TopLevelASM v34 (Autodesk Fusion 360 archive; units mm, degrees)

design "TopLevelASM" references "TopLevelMasterSketch", "BottleLidHolderASM", "HousingASM", "Rotational Option for Nozzle McM", "CYLHousingASM", "WaterSupplySystemASM", "DrainASM"
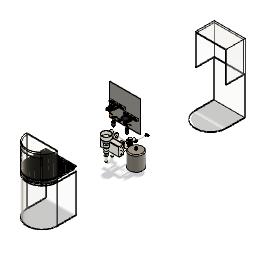
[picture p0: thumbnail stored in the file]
component_insert "Component Insert1"
ground "Ground1"
component_insert "Component Insert3"
ground "Ground2"
ground "Ground3"
ground "Ground6"
position "Position1"
component_insert "Component Insert5"
position "Position2"
component_insert "Component Insert6"
component_insert "Component Insert7"
component_insert "Component Insert8"
joint "Assemble1" alignAngle 0 alignOffsetX 0 alignOffsetY 0 alignOffsetZ 0
component_insert "Component Insert9"
position "Position3"
sketch "Sketch1" plane through (0, 0, -392.3651) normal (0, 0, -1) x axis (-1, 0, 0)
  circle C1 centre (-172.7691, -295.3633) radius 14.2875
  circle C2 centre (-172.7691, -295.3633) radius 15.875
  circle C3 centre (-172.7691, -295.3633) radius 14.2875
  circle C4 centre (-172.7691, -295.3633) radius 15.875
extrude "Extrude1" new body sketch "Sketch1" along normal blind 114.3
joint "Assemble3" alignAngle 180 alignOffsetX 0 alignOffsetY 0 alignOffsetZ 0
position "Position4"
position "Position5"
step "Context"
as_built_joint "As-built5"
position "Position7"
as_built_joint "As-built6"
component_insert "Component Insert12"
ground "Ground12"
as_built_joint "As-built7"

design "FrontPlumbingPanel" references "HousingMasterSketch"
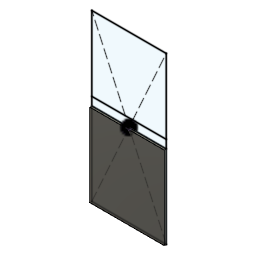
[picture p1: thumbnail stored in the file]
parameter "PlumbingPanelThickness" = 12.7
component_insert "Component Insert"
extrude "Extrude1" new body blind 12.7 (= "PlumbingPanelThickness")

design "LidHolderASM" references "LHGripperShort", "LHRail", "LHRubberMaterial", "LHGripperLong", "LHSlider"
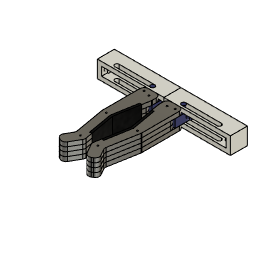
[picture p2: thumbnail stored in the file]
component_insert "Component Insert1"
component_insert "Component Insert2"
component_insert "Component Insert3"
component_insert "Component Insert4"
component_insert "Component Insert5"
component_insert "Component Insert6"
ground "Ground1"
joint "Assemble1" alignAngle 0 alignOffsetX 0 alignOffsetY 0 alignOffsetZ -6.35
joint "Assemble2" alignAngle 0 alignOffsetX 0 alignOffsetY 0 alignOffsetZ 0
joint "Assemble3" alignAngle 0 alignOffsetX 0 alignOffsetY 0 alignOffsetZ 0
joint "Assemble4" alignAngle 0 alignOffsetX 0 alignOffsetY 0 alignOffsetZ 0
joint "Assemble5" alignAngle 0 alignOffsetX 0 alignOffsetY 0 alignOffsetZ 0 SlideMinimum 0 SlideMaximum 53.34
component_insert "Component Insert7"
joint "Assemble8" alignAngle 0 alignOffsetX 0 alignOffsetY 0 alignOffsetZ 0
mirror_component "MirrorComponent1"
derived_instance "DerivedInstance6"
derived_instance "DerivedInstance7"
derived_instance "DerivedInstance1"
derived_instance "DerivedInstance4"
derived_instance "DerivedInstance1"
derived_instance "DerivedInstance4"
derived_instance "DerivedInstance3"
derived_instance "DerivedInstance4"
derived_instance "DerivedInstance5"
derived_instance "DerivedInstance8"
derived_instance "DerivedInstance2"
derived_instance "DerivedInstance10"
derived_instance "DerivedInstance2"
derived_instance "DerivedInstance8"
as_built_joint "As-built1"
ground "Ground2"
joint "Assemble6" alignAngle 0 alignOffsetX 0 alignOffsetY 0 alignOffsetZ 0 SlideMinimum 0 SlideMaximum 53.34
motion_link "MotionLink1" Value1 10.0076 Value2 10.0076
sketch "Sketch1" plane through (0, 0, 0) normal (0, 0, 1) x axis (1, 0, 0)
  circle C1 centre (0, 0) radius 24.13
  circle C2 centre (0, 0) radius 44.45
  point P1 (0, 0)
  point P2 (0, 0)
  coincident P1 P2
  concentric C1 C2
  dimension "d31" diameter C1 = 48.26
  dimension "d32" diameter C2 = 88.9
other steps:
derived_base_feature "Derived Base Feature1"
derived_base_feature "Derived Base Feature1"
derived_base_feature "Derived Base Feature1"
derived_base_feature "Derived Base Feature1"
derived_base_feature "Derived Base Feature1"
derived_base_feature "Derived Base Feature1"
derived_base_feature "Derived Base Feature1"
derived_base_feature "Derived Base Feature1"
derived_base_feature "Derived Base Feature1"
derived_base_feature "Derived Base Feature1"
create_component "CreateComponent1"
create_component "CreateComponent2"
create_component "CreateComponent3"
create_component "CreateComponent5"
create_component "CreateComponent6"
create_component "CreateComponent7"
create_component "CreateComponent8"
create_component "CreateComponent9"
create_component "CreateComponent10"
joint_origin "JointOrigin5"
joint_origin "JointOrigin5"
create_component "CreateComponent12"
create_component "CreateComponent13"
create_component "CreateComponent15"
create_component "CreateComponent16"
create_component "CreateComponent17"

design "BHGripperShort" references "BottleHolderMasterSketch"
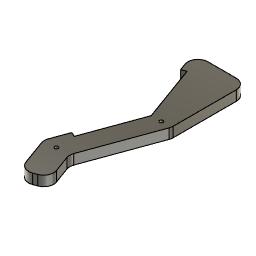
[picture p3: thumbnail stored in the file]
component_insert "Component Insert"
extrude "Extrude1" new body blind 6.35
sketch "Sketch1" plane through (0, 0, 0) normal (0, 0, 1) x axis (1, 0, 0)
  point P2 (32.253, 0)
  point P4 (32.253, 0)
  point P3 (13.189, -47.7364)
  point P5 (13.189, -47.7364)
  coincident P2 P4
  coincident P3 P5
hole "Hole1" HoleDepth 6.35 HoleDiameter 2.2606 TipAngle 118
fillet "Fillet1" radius 6.35
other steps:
create_component "CreateComponent1"

design "TopLevelMasterSketch"
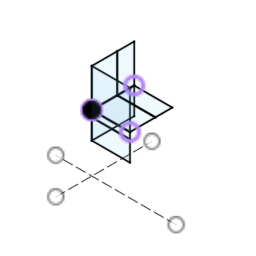
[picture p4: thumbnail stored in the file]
parameter "UIheight" = 457.2 comment "height of the encloser that users will use"
parameter "UIwidth" = 457.2 comment "width of the enclosure that users will interact with"
parameter "UIdepth" = 304.8 comment "depth of the enslosure that users will interract with"
parameter "ElectronicPanelHeight" = 76.2
parameter "ADAHeightOffGround" = 685.8 comment "ADA requirement (usually for the bottom of the water fountain part"
parameter "UnitHeightOffGround" = 368.3
parameter "BackAreaDepth" = 203.2 comment "this is the area behind the UI area where electronics and plumbing can be found"
parameter "Nozheight" = 160.02 comment "height of nozzle including threaded connector"
parameter "Nozdepth" = 38.608 comment "depth of nozzle asm"
parameter "Nozwidth" = 121.92 comment "nozzle width"
sketch "Sketch2" plane through (0, 0, 0) normal (0, 0, 1) x axis (1, 0, 0)
  line L1 (457.2, 0) -> (0, 0)
  line L2 (457.2, 457.2) -> (457.2, 0)
  line L3 (0, 457.2) -> (457.2, 457.2)
  line L4 (0, 0) -> (0, 457.2)
  line L5 (457.2, 0) -> (0, 0)
  line L6 (457.2, -76.2) -> (457.2, 0)
  line L7 (0, -76.2) -> (457.2, -76.2)
  line L8 (0, 0) -> (0, -76.2)
  line L9 (-431.8, -685.8) -> (1010.5119, -685.8)
  line L10 (457.2, -76.2) -> (0, -76.2)
  line L11 (457.2, -317.5) -> (457.2, -76.2)
  line L12 (0, -317.5) -> (457.2, -317.5)
  line L13 (0, -76.2) -> (0, -317.5)
  point P1 (0, 0)
  point P2 (0, 0)
  point P6 (0, 0)
  point P3 (457.2, 0)
  point P5 (0, 457.2)
  point P9 (0, -76.2)
  horizontal L1
  vertical L2
  horizontal L3
  vertical L4
  coincident P1 P2
  horizontal L5
  vertical L6
  horizontal L7
  vertical L8
  coincident P1 P6
  collinear L2 L6
  horizontal L9
  horizontal L10
  vertical L11
  horizontal L12
  vertical L13
  collinear L6 L11
  dimension "d6" distance P2 P3 = 457.2 (= "UIwidth")
  dimension "d7" distance P2 P5 = 457.2 (= "UIheight")
  dimension "d9" distance P6 P9 = 76.2 (= "ElectronicPanelHeight")
  dimension "d12" distance L5 L9 = 685.8 (= "ADAHeightOffGround")
  dimension "d15" distance L9 L12 = 368.3 (= "UnitHeightOffGround")
sketch "Sketch3" plane through (0, 0, 0) normal (1, 0, 0) x axis (0, 0, -1)
  line L1 (304.8, 0) -> (0, 0)
  line L2 (304.8, 457.2) -> (304.8, 0)
  line L3 (0, 457.2) -> (304.8, 457.2)
  line L4 (0, 0) -> (0, 457.2)
  line L5 (508, 0) -> (304.8, 0)
  line L6 (508, 457.2) -> (508, 0)
  line L7 (304.8, 457.2) -> (508, 457.2)
  line L8 (304.8, 0) -> (304.8, 457.2)
  line L9 (720.6658, -685.8) -> (-431.8, -685.8)
  line L10 (508, 0) -> (0, 0)
  line L11 (508, -317.5) -> (508, 0)
  line L12 (0, -317.5) -> (508, -317.5)
  line L13 (0, 0) -> (0, -317.5)
  point P1 (0, 0)
  point P2 (0, 0)
  point P11 (0, 0)
  point P3 (304.8, 0)
  point P6 (508, 0)
  horizontal L1
  vertical L2
  horizontal L3
  vertical L4
  coincident P1 P2
  horizontal L5
  vertical L6
  horizontal L7
  vertical L8
  collinear L3 L7
  horizontal L9
  horizontal L10
  vertical L11
  horizontal L12
  vertical L13
  coincident P1 P11
  collinear L6 L11
  dimension "d16" distance P2 P3 = 304.8 (= "UIdepth")
  dimension "d17" distance L1 L3 = 457.2 (= "UIheight")
  dimension "d19" distance P3 P6 = 203.2 (= "BackAreaDepth")
  dimension "d20" distance L9 L12 = 368.3 (= "UnitHeightOffGround")
  dimension "d21" distance L5 L9 = 685.8 (= "ADAHeightOffGround")
sketch "Sketch4" plane through (0, 0, 0) normal (0, 1, 0) x axis (1, 0, 0)
  line L1 (457.2, 0) -> (0, 0)
  line L2 (457.2, 304.8) -> (457.2, 0)
  line L3 (0, 304.8) -> (457.2, 304.8)
  line L4 (0, 0) -> (0, 304.8)
  line L5 (0, 508) -> (0, 0)
  line L6 (0, 0) -> (457.2, 0)
  line L7 (457.2, 304.8) -> (0, 304.8)
  line L8 (457.2, 508) -> (457.2, 304.8)
  line L9 (0, 508) -> (457.2, 508)
  line L10 (0, 304.8) -> (0, 508)
  point P2 (0, 0)
  point P8 (0, 0)
  point P3 (457.2, 0)
  horizontal L1
  vertical L2
  horizontal L3
  vertical L4
  coincident P2 L5
  coincident P2 P8
  horizontal L7
  vertical L8
  horizontal L9
  vertical L10
  collinear L2 L8
  dimension "d22" distance P2 P3 = 457.2 (= "UIwidth")
  dimension "d23" distance L3 L6 = 304.8 (= "UIdepth")
  dimension "d24" distance L3 L9 = 203.2 (= "BackAreaDepth")

design "HousingASM" references "TopBackHousing", "UIASM", "FrontPlumbingPanel", "BottomHousing", "UIButtonHousing", "HousingMasterSketch"
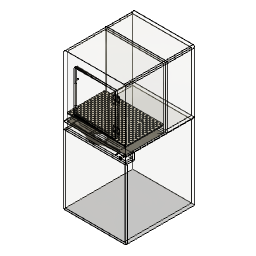
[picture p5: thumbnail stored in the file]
component_insert "Component Insert1"
component_insert "Component Insert2"
component_insert "Component Insert3"
component_insert "Component Insert4"
component_insert "Component Insert5"
ground "Ground1"
ground "Ground2"
position "Position1"
component_insert "Component Insert6"
position "Position2"
position "Position3"
as_built_joint "As-built7"
position "Position4"
as_built_joint "As-built8"
as_built_joint "As-built9"
as_built_joint "As-built10"
position "Position5"
as_built_joint "As-built11"

design "BHRail" references "BottleHolderMasterSketch"
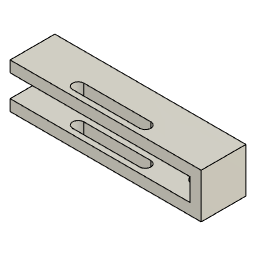
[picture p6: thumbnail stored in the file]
component_insert "Component Insert"
extrude "Extrude1" new body to an object
extrude "Extrude2" to an object
extrude "Extrude3" cut no distance stored
extrude "Extrude4" to an object
sketch "Sketch1" plane through (0, 73.1364, 0) normal (0, -1, 0) x axis (1, 0, 0)
  line L1 (102.1727, 6.35) -> (102.1727, -6.35)
  line L2 (0, 6.35) -> (102.1727, 6.35)
  line L3 (0, -6.35) -> (0, 6.35)
  line L4 (102.1727, -6.35) -> (0, -6.35)
hole "Hole1" HoleDepth 12.7 HoleDiameter 2.2606 TipAngle 118 CBDepth 1.2954 CBDiameter 3.81
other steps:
create_component "CreateComponent1"

design "CYLHousingASM" references "CYLUITopShell", "CYLPlumbingFrontPlate", "CYLPlumbingBackPlate", "CYLButtonPanel", "CYLDoor", "CYLDoorHandle", "CYLGrate", "UIBackPlate", "CYLDrainPlate"
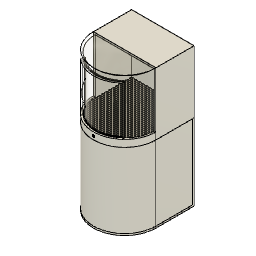
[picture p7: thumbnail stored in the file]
component_insert "Component Insert1"
ground "Ground1"
component_insert "Component Insert2"
as_built_joint "As-built1"
component_insert "Component Insert3"
component_insert "Component Insert4"
as_built_joint "As-built3"
component_insert "Component Insert5"
component_insert "Component Insert6"
position "Position1"
as_built_joint "As-built4"
as_built_joint "As-built6" OffsetX 0 OffsetY 0 OffsetZ 0 AngleZ 0 RotateMinimum 0 RotateMaximum 75
component_insert "Component Insert7"
component_insert "Component Insert8"
component_insert "Component Insert9"
position "Position2"
as_built_joint "As-built7"
as_built_joint "As-built8"
as_built_joint "As-built9"
position "Position3"

design "1/2FIPto3/4FIP"
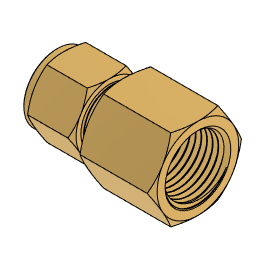
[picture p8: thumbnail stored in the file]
base_feature "Base Feature"
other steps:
create_component "CreateComponent1"

design "PeristalticPump"
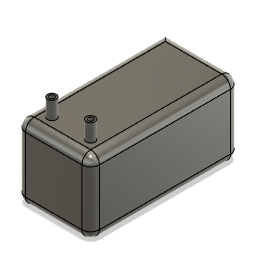
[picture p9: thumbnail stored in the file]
sketch "Sketch1" plane through (0, 0, 0) normal (0, 1, 0) x axis (1, 0, 0)
  line L1 (42, 0) -> (0, 0)
  line L2 (42, -84.4) -> (42, 0)
  line L3 (0, -84.4) -> (42, -84.4)
  line L4 (0, 0) -> (0, -84.4)
  point P1 (0, 0)
  point P2 (0, 0)
  point P3 (42, 0)
  point P5 (0, -84.4)
  horizontal L1
  vertical L2
  horizontal L3
  vertical L4
  coincident P1 P2
  dimension "d1" distance P2 P3 = 42
  dimension "d2" distance P2 P5 = 84.4
extrude "Extrude1" new body sketch "Sketch1" along normal blind 41.9
sketch "Sketch2" plane through (0, 0, 0) normal (0, 1, 0) x axis (1, 0, 0)
  line L1 (0, -84.4) -> (42, -84.4)
  line L2 (0, 0) -> (0, -84.4)
  line L3 (42, -84.4) -> (42, 0)
  circle C1 centre (10, -74.4) radius 2.5
  circle C2 centre (32, -74.4) radius 2.5
  circle C3 centre (10, -74.4) radius 1.5
  circle C4 centre (32, -74.4) radius 1.5
  point P2 (10, -74.4)
  point P3 (32, -74.4)
  concentric C1 C3
  concentric C2 C4
  dimension "d5" diameter C1 = 5
  dimension "d6" diameter C2 = 5
  dimension "d7" distance P2 L1 = 10
  dimension "d8" distance P2 L2 = 10
  dimension "d9" distance P3 L3 = 10 (= "d8")
  dimension "d10" distance P3 L1 = 10 (= "d7")
  dimension "d16" diameter C3 = 3
  dimension "d17" diameter C4 = 3
extrude "Extrude2" add sketch "Sketch2" profile of C1 C2 C3 C4 blind 10 from offset 41.9
fillet "Fillet1" radius 5

design "Water Heater body"
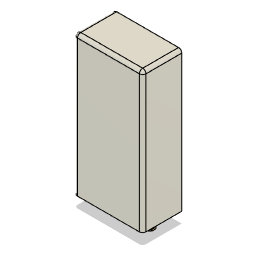
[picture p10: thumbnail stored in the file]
sketch "Sketch1" plane through (0, 0, 0) normal (0, 0, 1) x axis (1, 0, 0)
  line L1 (-66.675, 136.525) -> (66.675, 136.525)
  line L2 (-66.675, -136.525) -> (-66.675, 136.525)
  line L3 (66.675, -136.525) -> (-66.675, -136.525)
  line L4 (66.675, 136.525) -> (66.675, -136.525)
  line L5 (-66.675, -136.525) -> (66.675, 136.525)
  line L6 (66.675, -136.525) -> (-66.675, 136.525)
  point P1 (0, 0)
  point P2 (0, 0)
  point P7 (0, 0)
  point P5 (-66.675, -136.525)
  point P6 (66.675, -136.525)
  point P4 (-66.675, 136.525)
  coincident P1 P2
  horizontal L1
  perpendicular L1 L2
  parallel L1 L3
  parallel L2 L4
  coincident L5 P7
  coincident L6 P7
  coincident P2 P7
  dimension "d1" distance P5 P6 = 133.35
  dimension "d2" distance P4 P5 = 273.05
extrude "Extrude1" new body sketch "Sketch1" profile of L1 L2 L3 L4 along normal blind 76.2 bodies "Heater shell"
sketch "Sketch2" plane through (0, -136.525, 0) normal (0, -1, 0) x axis (1, 0, 0)
  line L1 (66.675, 0) -> (-66.675, 0)
  line L2 (66.675, 76.2) -> (66.675, 0)
  line L3 (-66.675, 76.2) -> (66.675, 76.2)
  line L4 (-66.675, 0) -> (-66.675, 76.2)
  line L5 (66.675, 76.2) -> (-66.675, 76.2)
  line L6 (66.675, 0) -> (66.675, 76.2)
  line L7 (-66.675, 0) -> (66.675, 0)
  line L8 (-66.675, 76.2) -> (-66.675, 0)
  line L9 (-22.225, 38.1) -> (-66.675, 38.1)
  line L10 (22.225, 38.1) -> (-22.225, 38.1)
  line L11 (66.675, 38.1) -> (22.225, 38.1)
  circle C1 centre (-44.45, 38.1) radius 4.7625
  circle C2 centre (0, 38.1) radius 4.7625
  circle C3 centre (44.45, 38.1) radius 4.7625
  point P3 (66.675, 0)
  point P8 (66.675, 0)
  point P5 (-66.675, 76.2)
  point P6 (-66.675, 76.2)
  point P10 (-66.675, 38.1)
  point P13 (-44.45, 38.1)
  point P14 (0, 38.1)
  point P15 (66.675, 38.1)
  point P16 (44.45, 38.1)
  point P11 (-22.225, 38.1)
  point P12 (22.225, 38.1)
  horizontal L5
  vertical L6
  horizontal L7
  vertical L8
  coincident P3 P8
  coincident P5 P6
  midpoint L8 P10
  perpendicular L4 L9
  parallel L9 L10
  midpoint L9 P13
  midpoint L10 P14
  midpoint L6 P15
  midpoint L11 P16
  dimension "d5" distance P10 P11 = 44.45
  dimension "d6" distance P11 P12 = 44.45
  dimension "d7" diameter C1 = 9.525 (= "( 3 / 8 ) * 1 in")
  dimension "d8" diameter C2 = 9.525 (= "( 3 / 8 ) * 1 in")
  dimension "d9" diameter C3 = 9.525 (= "( 3 / 8 ) * 1 in")
sketch "Sketch3" plane through (0, 0, 0) normal (0, 0, -1) x axis (-1, 0, 0)
  line L1 (-66.675, -136.525) -> (-66.675, 136.525)
  line L2 (66.675, -136.525) -> (-66.675, -136.525)
  line L3 (66.675, 136.525) -> (66.675, -136.525)
  line L4 (-66.675, 136.525) -> (66.675, 136.525)
  line L5 (-66.675, -136.525) -> (66.675, -136.525)
  line L6 (-66.675, 136.525) -> (-66.675, -136.525)
  line L7 (66.675, 136.525) -> (-66.675, 136.525)
  line L8 (66.675, -136.525) -> (66.675, 136.525)
  line L9 (-66.675, 136.525) -> (66.675, -136.525)
  line L10 (66.675, 136.525) -> (-66.675, -136.525)
  line L11 (-53.975, 136.525) -> (-66.675, 136.525)
  line L12 (-53.975, 123.825) -> (-53.975, 136.525)
  circle C1 centre (-53.975, 123.825) radius 3.175
  circle C2 centre (53.975, 123.825) radius 3.175
  circle C3 centre (-53.975, -123.825) radius 3.175
  circle C4 centre (53.975, -123.825) radius 3.175
  point P10 (0, 0)
  point P4 (66.675, -136.525)
  point P6 (66.675, -136.525)
  point P1 (0, 0)
  point P12 (-53.975, 123.825)
  point P13 (-53.975, 123.825)
  point P8 (-66.675, 136.525)
  point P11 (-53.975, 136.525)
  horizontal L5
  perpendicular L5 L6
  parallel L5 L7
  parallel L6 L8
  coincident L9 P10
  coincident L10 P10
  coincident P4 P6
  coincident P1 P10
  perpendicular L1 L11
  perpendicular L7 L12
  coincident P12 P13
  dimension "d10" distance P8 P11 = 12.7
  dimension "d11" distance P11 P12 = 12.7
  dimension "d12" diameter C1 = 6.35
  dimension "d15" R-Pattern1-uDistance = 107.95
  dimension "d16" R-Pattern1-vDistance = -247.65
shell "Shell1" innerThickness 3.175
extrude "Extrude2" cut sketch "Sketch3" profile of C1 C2 C3 C4 against normal blind 25.4
extrude "Extrude3" cut sketch "Sketch2" profile of L9 L10 C1 C2 L11 C3 against normal blind 6.35
base_feature "Base Feature1"
base_feature "Base Feature1"
work_plane "WorkPlane1" AlongDistance 0
split "Split1"
remove_body "RemoveBody1"
remove_body "RemoveBody2"
remove_body "RemoveBody3"
copy_paste "CopyPaste1"
fillet "Fillet1" radius 6.35
fillet "Fillet2" radius 6.35
fillet "Fillet3" radius 6.35
joint "Assemble1" alignAngle 0 alignOffsetX 7.62 alignOffsetY 0 alignOffsetZ 0
joint "Assemble2" alignAngle 180 alignOffsetX 2.54 alignOffsetY 5.08 alignOffsetZ 0
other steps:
create_component "CreateComponent1"
create_component "CreateComponent1"
joint_origin "JointOrigin1"
joint_origin "JointOrigin1"
joint_origin "JointOrigin2"
joint_origin "JointOrigin2"
named bodies: "Heater shell"

design "LHRail" references "LidHolderMasterSketch"
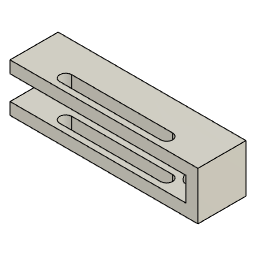
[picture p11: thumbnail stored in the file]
component_insert "Component Insert"
extrude "Extrude1" new body to an object
extrude "Extrude2" to an object
extrude "Extrude3" cut no distance stored
extrude "Extrude4" to an object
sketch "Sketch1" plane through (0, 75.438, 0) normal (0, -1, 0) x axis (1, 0, 0)
  line L1 (92.8878, 6.35) -> (92.8878, -6.35)
  line L2 (0, 6.35) -> (92.8878, 6.35)
  line L3 (0, -6.35) -> (0, 6.35)
  line L4 (92.8878, -6.35) -> (0, -6.35)
hole "Hole1" HoleDepth 12.7 HoleDiameter 2.2606 TipAngle 118 CBDepth 1.2954 CBDiameter 3.81
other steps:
create_component "CreateComponent1"

design "CYLDoorHandle" references "CYLDoor"
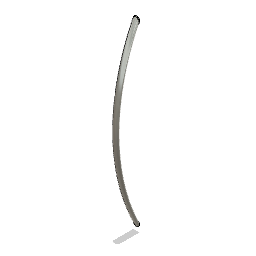
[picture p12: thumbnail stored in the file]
component_insert "Component Insert"
sketch "Sketch3" plane through (0, 0, 0) normal (0, 0, 1) x axis (1, 0, 0)
  circle C1 centre (0, 177.8) radius 3.175
  circle C2 centre (0, 0) radius 3.175
  point P2 (0, 177.8)
  point P3 (0, 0)
  point P1 (0, 0)
  vertical P2 P3
  vertical P1 P3
  equal C1 C2
  coincident P1 P3
  dimension "d8" diameter C1 = 6.35
  dimension "d9" distance P2 P3 = 177.8
sketch "Sketch4" plane through (0, 0, 0) normal (1, 0, 0) x axis (0, 0, -1)
  line L1 (0, 174.625) -> (0, 180.975)
  circle C1 centre (182.7212, 88.9) radius 203.2
  point P4 (0, 177.8)
  point P6 (0, 0)
  coincident P4 C1
  coincident C1 P6
  dimension "d11" diameter C1 = 406.4
sweep "Sweep1" sketch "Sketch3" TwistAngle 0 TaperAngle 0
position "Position1"
sketch "Sketch5" plane through (0, 0, 0) normal (0, 1, 0) x axis (1, 0, 0)
  line L1 (194.359, 157.3581) -> (200.4927, 155.7146)
  line L2 (-56.1526, 7.5404) -> (-54.5091, 13.674)
  arc A1 centre (-1.9171, 209.9502) radius 209.55 clockwise from (200.4927, 155.7146) to (-56.1526, 7.5404)
  arc A2 centre (-1.9171, 209.9502) radius 203.2 clockwise from (194.359, 157.3581) to (-54.5091, 13.674)
extrude "Extrude2" cut sketch "Sketch5" no distance stored
ground "Ground1"
as_built_joint "As-built1"

design "Rotational Option for Nozzle McM" references "One-Way Rotating Flow Joint (3/8)"
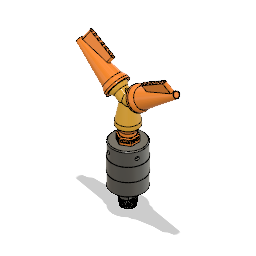
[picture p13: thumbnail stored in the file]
base_feature "Base Feature1" bodies "5307K24"
base_feature "Base Feature1" bodies "10095K36"
position "Position1"
copy_paste "CopyPaste1"
move "Move1"
move "Move2"
move "Move3"
position "Position2"
sketch "Sketch1" plane through (0, -36.992, 0) normal (0, -1, 0) x axis (1, 0, 0)
  circle C1 centre (-43.5581, 0) radius 11.011
  circle C2 centre (-43.5581, 0) radius 10.196
  circle C3 centre (-43.5581, 0) radius 2.54
  concentric C1 C3
  dimension "d1" diameter C3 = 5.08
extrude "Extrude1" cut sketch "Sketch1" profile of C3 against normal blind 127
sketch "Sketch2" plane through (0, -36.992, 0) normal (0, -1, 0) x axis (1, 0, 0)
  circle C1 centre (-43.5581, 0) radius 11.011
  circle C2 centre (-43.5581, 0) radius 10.196
  circle C3 centre (-43.5581, 0) radius 10.196
  circle C4 centre (-43.5581, 0) radius 11.196
  dimension "d4" = 1
base_feature "Base Feature1" bodies "10095K32"
move "Move4"
component_insert "Component Insert"
joint "Assemble2" alignAngle 0 alignOffsetX 0 alignOffsetY 0 alignOffsetZ 0
joint "Assemble3" alignAngle 90 alignOffsetX 0 alignOffsetY 0 alignOffsetZ 0 RotateMinimum 0 RotateMaximum 0
joint "Assemble4" alignAngle 20 alignOffsetX 0 alignOffsetY 0 alignOffsetZ 0
joint "Assemble5" alignAngle 20 alignOffsetX 0 alignOffsetY 0 alignOffsetZ 0
joint "Assemble1" alignAngle 0 alignOffsetX 0 alignOffsetY 0 alignOffsetZ 0 SlideMinimum 0 SlideMaximum 25.4
extrude "Extrude2" add sketch "Sketch2" profile of C1 C2 C3 along normal blind 12.7
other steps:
create_component "CreateComponent1"
create_component "CreateComponent2"
create_component "CreateComponent3"
joint_origin "JointOrigin1"
joint_origin "JointOrigin2"
joint_origin "JointOrigin1"
joint_origin "JointOrigin3"
joint_origin "JointOrigin2"
joint_origin "JointOrigin3"
joint_origin "JointOrigin3"
joint_origin "JointOrigin4"
named bodies: "5307K24", "10095K36", "10095K32"

design "PeristalticPumpASM" references "T-Fitting-3/8-3/8", "PeristalticPump", "DetergentTank"
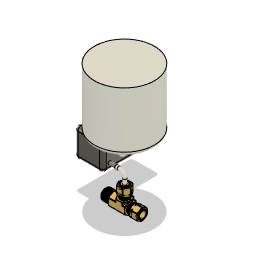
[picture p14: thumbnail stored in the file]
component_insert "Component Insert1"
ground "Ground1"
component_insert "Component Insert4"
position "Position1"
ground "Ground2"
component_insert "Component Insert5"
ground "Ground3"
ground "Ground4"
sketch "Sketch2" plane through (0, 0, 0) normal (0, 0, 1) x axis (1, 0, 0)
  line L1 (-5.7052, 36.576) -> (7.2624, 36.576)
  line L2 (-2.5, 89.1085) -> (2.5, 89.1085)
  line L3 (0, 76.4085) -> (0, 89.1085)
  line L4 (-84.7565, 80.7261) -> (-52.8565, 80.7261)
  line L5 (-8.0505, 74.237) -> (-8.0505, 52.2406)
  line L6 (-11.8605, 52.2406) -> (-8.0505, 52.2406)
  line L7 (-11.8605, 74.237) -> (-8.0505, 74.237)
  line L8 (0.7786, 43.8805) -> (0.7786, 36.576)
  arc A1 centre (-4.3181, 76.4085) radius 4.3181 clockwise from (0, 76.4085) to (-8.0505, 74.237)
  arc A2 centre (-7.594, 43.8805) radius 8.3726 clockwise from (-8.0505, 52.2406) to (0.7786, 43.8805)
  point P7 (0, 89.1085)
  point P16 (0.7786, 36.576)
  point P8 (0, 76.4085)
  point P9 (-8.0505, 52.2406)
  point P10 (-8.0505, 74.237)
  point P14 (-11.8605, 52.2406)
  point P15 (-11.8605, 74.237)
  midpoint L2 P7
  perpendicular L2 L3
  tangent L3 A1
  perpendicular L4 L5
  perpendicular L5 L6
  perpendicular L5 L7
  midpoint L1 P16
  perpendicular L1 L8
  tangent L8 A2
  dimension "d2" distance P7 P8 = 12.7
  dimension "d4" distance P9 P10 = 21.9964
  dimension "d23" distance P9 P14 = 3.81
  dimension "d25" distance P10 P15 = 3.81
sketch "Sketch4" plane through (0.7786, 36.83, 0.2778) normal (0, 1, 0) x axis (0, 0, 1)
  circle C1 centre (0, 0) radius 5.8706
  circle C2 centre (0, 0) radius 4.8514
  circle C3 centre (0, 0) radius 2.5
  circle C4 centre (0, 0) radius 1.5
  concentric C1 C3
  concentric C3 C4
  dimension "d7" diameter C3 = 5
  dimension "d14" diameter C4 = 3
sweep "Sweep1" sketch "Sketch4" TwistAngle 0 TaperAngle 0
sketch "Sketch5" plane through (0, 89.1085, 0) normal (0, -1, 0) x axis (1, 0, 0)
  circle C1 centre (0, 0) radius 5.675
  circle C2 centre (0, 0) radius 2.5
  circle C3 centre (0, 0) radius 0.5
  circle C4 centre (0, 0) radius 2.5
  point P1 (0, 0)
  point P3 (0, 0)
  point P4 (0, 0)
  coincident P1 P3
  coincident P1 P4
  dimension "d15" diameter C3 = 1 (= "mm")
  dimension "d16" diameter C4 = 5
sweep "Sweep2" sketch "Sketch5" TwistAngle 0 TaperAngle 0
ground "Ground5"
joint "Assemble1" alignAngle -90 alignOffsetX 0 alignOffsetY 0 alignOffsetZ 0
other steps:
joint_origin "JointOrigin1"

design "WaterSupplySystemASM" references "3/8compTo3/8MNTP", "PeristalticPumpASM", "T-Fitting-3/8-3/8", "AccumulatorASM", "Water Heater body", "BZW-10-110VAC", "NozzleSetUpASM"
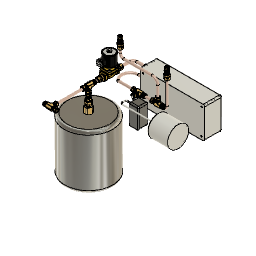
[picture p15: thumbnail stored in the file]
component_insert "Component Insert1"
sketch "Sketch1" plane through (0, 36.83, 0) normal (0, 1, 0) x axis (-1, 0, 0)
  circle C1 centre (-0.7786, 0.2778) radius 5.8706
  circle C2 centre (-0.7786, 0.2778) radius 4.8514
  circle C3 centre (-0.7786, 0.2778) radius 4.8514
  circle C4 centre (-0.7786, 0.2778) radius 3.175
  concentric C3 C4
  dimension "d1" diameter C4 = 6.35
extrude "Extrude1" new body sketch "Sketch1" profile of C2 C3 C4 along normal blind 114.3
component_insert "Component Insert2"
joint "Assemble1" alignAngle 0 alignOffsetX 0 alignOffsetY 0 alignOffsetZ 0
component_insert "Component Insert3"
component_insert "Component Insert4"
component_insert "Component Insert8"
position "Position1"
work_plane "WorkPlane1" AlongDistance 0
position "Position2"
component_insert "Component Insert11"
position "Position5"
sketch "Sketch5" plane through (0, 197.2031, 0) normal (0, 1, 0) x axis (-1, 0, 0)
  circle C1 centre (-0.7786, 0.2778) radius 7.0282
  circle C2 centre (-0.7786, 0.2778) radius 3.9624
  circle C3 centre (-0.7786, 0.2778) radius 3.175
  circle C4 centre (-0.7786, 0.2778) radius 4.7625
  concentric C3 C4
  dimension "d19" diameter C4 = 9.525
extrude "Extrude3" new body sketch "Sketch5" profile of C2 C3 C4 along normal blind 12.7
joint "Assemble3" alignAngle 0 alignOffsetX 0 alignOffsetY 0 alignOffsetZ 10.16
component_insert "Component Insert12"
component_insert "Component Insert13"
joint "Assemble4" alignAngle 180 alignOffsetX -7.62 alignOffsetY 2.54 alignOffsetZ 0
position "Position6"
sketch "Sketch7" plane through (0, 310.8886, 0) normal (0, 1, 0) x axis (-1, 0, 0)
  circle C1 centre (0.43, -0.4775) radius 8
  circle C2 centre (0.43, -0.4775) radius 5.75
  circle C3 centre (0.43, -0.4775) radius 4
  circle C4 centre (0.43, -0.4775) radius 5.5
extrude "Extrude4" new body sketch "Sketch7" profile of C3 C4 along normal blind 12.7 and against normal blind 7.62
sketch "Sketch9" plane through (0, 0, 0) normal (0, 0, 1) x axis (1, 0, 0)
  line L1 (-0.059, 343.4474) -> (-0.059, 323.52)
  line L2 (15.5736, 359.08) -> (35.501, 359.08)
  arc A1 centre (15.5736, 343.4474) radius 15.6326 clockwise from (-0.059, 343.4474) to (15.5736, 359.08)
  point P2 (-0.059, 323.52)
  point P4 (35.501, 359.08)
  point P3 (-0.059, 343.4474)
  point P5 (15.5736, 359.08)
  point P6 (15.5736, 343.4474)
  vertical L1
  horizontal L2
  tangent L2 A1
  dimension "d43" distance P2 L2 = 35.56
  dimension "d44" distance L1 P4 = 35.56
  dimension "d45" angle P3 P5 P6 = 135
sweep "Sweep1" TwistAngle 0 TaperAngle 0
sketch "Sketch10" plane through (35.501, 0, 0) normal (1, 0, 0) x axis (0, 1, 0)
  circle C1 centre (359.451, -0.4775) radius 4
  circle C2 centre (359.451, -0.4775) radius 5.5
  circle C3 centre (359.451, -0.4775) radius 4
  circle C4 centre (359.451, -0.4775) radius 5.5
extrude "Extrude5" add sketch "Sketch10" along normal blind 12.7
joint "Assemble5" alignAngle -90 alignOffsetX 0 alignOffsetY 0 alignOffsetZ 0
position "Position8"
work_plane "WorkPlane2" AlongDistance 299.0342
position "Position9"
work_plane "WorkPlane3" AlongDistance -42.926
sketch "Sketch12" plane through (0, 0, -42.926) normal (0, 0, 1) x axis (1, 0, 0)
  line L1 (23.9471, 352.6133) -> (61.1816, 352.6133)
  line L2 (63.5, 298.4972) -> (6.0432, 298.4972)
  arc A1 centre (23.9471, 322.5936) radius 30.0198 clockwise from (6.0432, 298.4972) to (23.9471, 352.6133)
  horizontal L1
  horizontal L2
  tangent L1 A1
sketch "Sketch13" plane through (60.774, 0, 0) normal (-1, 0, 0) x axis (0, 0, 1)
  circle C1 centre (-43.4161, 358.2258) radius 4.8514
  circle C2 centre (-43.4161, 358.2258) radius 3.9624
  circle C3 centre (-43.4161, 358.2258) radius 3.175
  circle C4 centre (-43.4161, 358.2258) radius 4.7625
  concentric C1 C3
  concentric C3 C4
  dimension "d78" diameter C3 = 6.35
  dimension "d79" diameter C4 = 9.525
component_insert "Component Insert16"
position "Position10"
joint "Assemble10" alignAngle 180 alignOffsetX 0 alignOffsetY 0 alignOffsetZ 0
joint "Assemble11" alignAngle -90 alignOffsetX 0 alignOffsetY 0 alignOffsetZ 0
sketch "Sketch16" plane through (90.9486, 311.8356, -43.6939) normal (0, 0, 1) x axis (-1, 0, 0)
  line L1 (0, 91.44) -> (0, 88.9)
  line L2 (-147.32, 96.52) -> (-4.8749, 96.52)
  line L3 (-251.8787, 109.1301) -> (-251.8787, -7.7623)
  arc A1 centre (-5.0843, 91.44) radius 5.0843 clockwise from (-4.8749, 96.52) to (0, 91.44)
  point P2 (0, 88.9)
  point P5 (-147.32, 96.52)
  vertical L1
  perpendicular L1 L2
  tangent L1 A1
  vertical L3
  dimension "d117" distance P2 L3 = 251.8787
  dimension "d118" distance P2 P5 = 147.32
sweep "Sweep4" TwistAngle 0 TaperAngle 0
joint "Assemble13" alignAngle -90 alignOffsetX 0 alignOffsetY 0 alignOffsetZ 0
sketch "Sketch17" plane through (118.618, 0, 0) normal (1, 0, 0) x axis (0, 1, 0)
  circle C1 centre (292.8847, -43.4161) radius 7.0282
  circle C2 centre (292.8847, -43.4161) radius 3.9624
  circle C3 centre (292.8847, -43.4161) radius 4.7625
  circle C4 centre (292.8847, -43.4161) radius 3.175
  concentric C1 C3
  concentric C3 C4
  dimension "d129" diameter C4 = 6.35
  dimension "d130" diameter C3 = 9.525
extrude "Extrude8" new body sketch "Sketch17" profile of C2 C3 C4 along normal blind 50.8
component_insert "Component Insert17"
joint "Assemble14" alignAngle 90 alignOffsetX 0 alignOffsetY 0 alignOffsetZ 0
sketch "Sketch18" plane through (0, 299.0342, 0) normal (0, 1, 0) x axis (1, 0, 0)
  line L1 (170.7316, -25.6891) -> (170.7316, 18.2038)
  line L2 (26.5745, -48.5385) -> (147.3117, -48.5385)
  line L3 (11.9955, -78.2355) -> (11.9955, -63.4661)
  line L4 (212.3507, -78.0535) -> (212.3507, 31.7721)
  line L5 (341.8304, -88.6121) -> (341.8304, 1.9611)
  line L6 (199.1099, 46.2076) -> (196.0232, 46.2076)
  arc A1 centre (26.9273, -63.4661) radius 14.9318 clockwise from (11.9955, -63.4661) to (26.5745, -48.5385)
  arc A2 centre (147.3117, -25.1114) radius 23.427 clockwise from (170.7316, -25.6891) to (147.3117, -48.5385)
  arc A3 centre (199.1099, 32.9173) radius 13.2903 clockwise from (199.1099, 46.2076) to (212.3507, 31.7721)
  vertical L1
  horizontal L2
  vertical L3
  tangent L3 A1
  tangent L2 A2
  vertical L4
  vertical L5
  perpendicular L3 L6
  tangent L6 A3
  dimension "d168" distance L3 L4 = 200.3552
sketch "Sketch20" plane through (0, 0, -30.4621) normal (0, 0, 1) x axis (-1, 0, 0)
  circle C1 centre (-170.688, -292.8847) radius 4.8514
  circle C2 centre (-170.688, -292.8847) radius 3.9624
  circle C3 centre (-170.688, -292.8847) radius 3.175
  circle C4 centre (-170.688, -292.8847) radius 4.7625
  concentric C1 C3
  concentric C1 C4
  dimension "d137" diameter C3 = 6.35
  dimension "d138" diameter C4 = 9.525
extrude "Extrude9" new body sketch "Sketch20" profile of C2 C3 C4 along normal blind 19.05
sketch "Sketch21" plane through (199.136, 0, 0) normal (1, 0, 0) x axis (0, 1, 0)
  circle C1 centre (292.8847, -43.4161) radius 7.0282
  circle C2 centre (292.8847, -43.4161) radius 3.9624
  circle C3 centre (292.8847, -43.4161) radius 4.7625
  circle C4 centre (292.8847, -43.4161) radius 3.175
  concentric C1 C3
  concentric C1 C4
  dimension "d141" diameter C4 = 6.35
  dimension "d142" diameter C3 = 9.525
extrude "Extrude10" new body sketch "Sketch21" profile of C2 C3 C4 along normal blind 2.54
sweep "Sweep5" TwistAngle 0 TaperAngle 0
sweep "Sweep6" TwistAngle 0 TaperAngle 0
joint "Assemble16" alignAngle 0 alignOffsetX 0 alignOffsetY 0 alignOffsetZ 0
joint "Assemble17" alignAngle -1 alignOffsetX 0 alignOffsetY 0 alignOffsetZ 0
position "Position11"
sketch "Sketch22" plane through (0, 320.2431, -0.8839) normal (0, -1, 0.0028) x axis (1, 0, 0)
  line L1 (68.9973, 23.7715) -> (335.6973, 23.7715)
  line L2 (68.9973, -109.5785) -> (68.9973, 23.7715)
  line L3 (335.6973, -109.5785) -> (68.9973, -109.5785)
  line L4 (342.0473, 17.4215) -> (342.0473, -103.2285)
  line L5 (215.9153, 88.9) -> (203.2, 88.9)
  line L6 (215.9153, 77.9385) -> (215.9153, 88.9)
  line L7 (203.2, 77.9385) -> (215.9153, 77.9385)
  line L8 (203.2, 88.9) -> (203.2, 77.9385)
  arc A1 centre (335.6973, 17.4215) radius 6.35 clockwise from (335.6973, 23.7715) to (342.0473, 17.4215)
  arc A2 centre (335.6973, -103.2285) radius 6.35 clockwise from (342.0473, -103.2285) to (335.6973, -109.5785)
  circle C1 centre (329.3473, -96.8785) radius 3.175
  circle C2 centre (81.6973, 11.0715) radius 3.175
  circle C3 centre (329.3473, 11.0715) radius 3.175
  circle C4 centre (81.6973, -96.8785) radius 3.175
  horizontal L5
  vertical L6
  horizontal L7
  vertical L8
extrude "Extrude11" cut sketch "Sketch22" profile of L5 L6 L7 L8 along normal blind 38.1
joint "Assemble18" alignAngle 0 alignOffsetX 0 alignOffsetY 0 alignOffsetZ 0
joint "Assemble19" alignAngle 90 alignOffsetX 0 alignOffsetY 0 alignOffsetZ 0
position "Position12"
sketch "Sketch23" plane through (0, 0, 0) normal (0, 0, 1) x axis (1, 0, 0)
  line L1 (63.754, 286.4009) -> (63.754, 299.3685)
  line L2 (26.685, 292.2558) -> (63.754, 292.2558)
  line L3 (-5.93, 343.4474) -> (5.07, 343.4474)
  line L4 (-0.1402, 343.4474) -> (0.0038, 319.4114)
  closed curve K1 centre (26.5735, 292.8847)
  arc A1 centre (26.685, 318.9412) radius 26.6854 clockwise from (26.685, 292.2558) to (0.0038, 319.4114)
  arc A2 centre (16.33, 343.5461) radius 16.4705 clockwise from (-0.1402, 343.4474) to (12.133, 359.4729)
  point P7 (63.754, 292.2558)
  point P8 (26.685, 292.2558)
  point P13 (-0.1402, 343.4474)
  point P14 (12.133, 359.4729)
  point P16 (12.133, 359.4729)
  coincident L1 P7
  coincident K1 P8
  horizontal L2
  tangent L2 A1
  coincident L3 P13
  tangent L4 A2
  coincident P14 P16
sketch "Sketch24" plane through (0.7121, 0, -110.3419) normal (-0.0065, 0, 1) x axis (0, -1, 0)
  circle C1 centre (-168.755, 0.8756) radius 13.3731
  circle C2 centre (-168.755, 0.8756) radius 88.9
sketch "Sketch25" plane through (11.371, 0, 0) normal (-1, 0, 0) x axis (0, 0, 1)
  circle C1 centre (-43.4161, 358.2258) radius 5.8706
  circle C2 centre (-43.4161, 358.2258) radius 4.8514
  circle C3 centre (-43.4161, 358.2258) radius 4.7625
  circle C4 centre (-43.4161, 358.2258) radius 3.175
  concentric C1 C3
  concentric C3 C4
  dimension "d183" diameter C3 = 9.525 (= "( 3 / 8 ) * 1 in")
  dimension "d184" diameter C4 = 6.35
sweep "Sweep7" sketch "Sketch25" TwistAngle 0 TaperAngle 0
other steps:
joint_origin "JointOrigin2"
joint_origin "JointOrigin6"
joint_origin "JointOrigin8"
joint_origin "JointOrigin13"
joint_origin "JointOrigin15"
joint_origin "JointOrigin16"
joint_origin "JointOrigin18"
joint_origin "JointOrigin28"
joint_origin "JointOrigin29"
joint_origin "JointOrigin30"

design "Bottle"
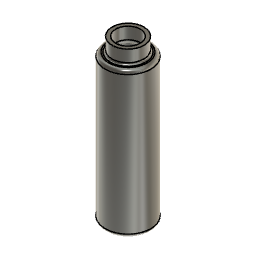
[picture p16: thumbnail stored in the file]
sketch "Sketch1" plane through (0, 0, 0) normal (0, 1, 0) x axis (1, 0, 0)
  line L1 (0, -265.2198) -> (0, 0)
  line L2 (31.75, 0) -> (0, 0)
  line L3 (31.75, -203.2) -> (31.75, 0)
  line L4 (22.225, -203.2) -> (31.75, -203.2)
  line L5 (22.225, -222.25) -> (22.225, -203.2)
  line L6 (0, -222.25) -> (22.225, -222.25)
  line L7 (0, 0) -> (0, -222.25)
  point P1 (0, 0)
  point P2 (0, 0)
  point P4 (0, 0)
  point P9 (0, -222.25)
  point P10 (0, 0)
  coincident P1 P2
  vertical L1
  coincident P1 P4
  perpendicular L1 L2
  perpendicular L2 L3
  perpendicular L3 L4
  perpendicular L4 L5
  coincident L1 P9
  perpendicular L1 L6
  coincident P1 P10
  dimension "d1" = 63.5
  dimension "d2" = 44.45 (= "d1 - 0.75 in")
  dimension "d3" distance L2 L4 = 203.2
  dimension "d5" distance L4 L6 = 19.05
revolve "Revolve1" sketch "Sketch1" AlongAngle 360
fillet "Fillet1" radius 5.08 2.54
shell "Shell1" innerThickness 5.08
sketch "Sketch2" plane through (0, 0, 222.25) normal (0, 0, 1) x axis (-1, 0, 0)
  circle C1 centre (0, 0) radius 22.225
  circle C2 centre (0, 0) radius 22.225
  circle C3 centre (0, 0) radius 17.145
  dimension "d12" = -5.08
extrude "Extrude1" cut sketch "Sketch2" profile of C3 against normal blind 38.1

design "3/8compTo3/8MNTP"
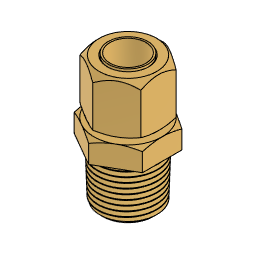
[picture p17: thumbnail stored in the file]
base_feature "Base Feature"
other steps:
create_component "CreateComponent1"

design "BackPanel" references "BottleLidHolderPlacementMasterSketch"
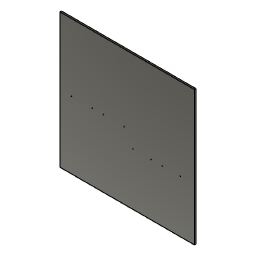
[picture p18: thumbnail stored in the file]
component_insert "Component Insert"
extrude "Extrude1" new body blind -5.08
sketch "Mounting Hole Pattern Sketch" plane through (0, 0, 0) normal (0, 1, 0) x axis (1, 0, 0)
hole "Hole1" HoleDepth 5.08 HoleDiameter 2.2606 TipAngle 118

design "UIBackPlate" references "UIMasterSketch"
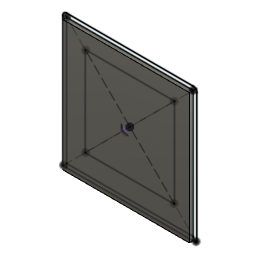
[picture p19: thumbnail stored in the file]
parameter "UIBackPlateThickness" = 12.7
component_insert "Component Insert"
extrude "Extrude3" new body blind 12.7
extrude "Extrude2" new body blind 12.7 (= "UIBackPlateThickness")
extrude "Extrude1" new body blind 12.7

design "PVCstepdown4to2"
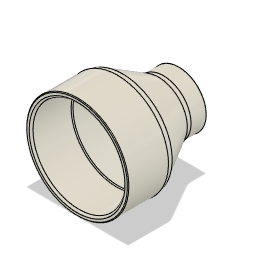
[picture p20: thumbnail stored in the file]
base_feature "Base Feature"
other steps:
create_component "CreateComponent1"

design "3/8compTo1/2MIP"
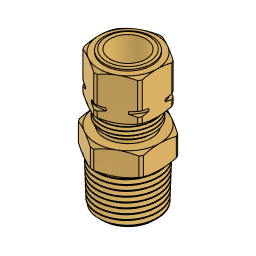
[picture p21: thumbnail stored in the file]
base_feature "Base Feature"
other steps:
create_component "CreateComponent1"

design "Lid"
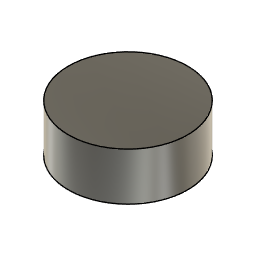
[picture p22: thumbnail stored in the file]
sketch "Sketch1" plane through (0, 0, 0) normal (0, 0, 1) x axis (1, 0, 0)
  circle C1 centre (0, 0) radius 31.75
  point P1 (0, 0)
  point P2 (0, 0)
  coincident P1 P2
  dimension "d1" diameter C1 = 63.5
extrude "Extrude1" new body sketch "Sketch1" along normal blind 25.4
